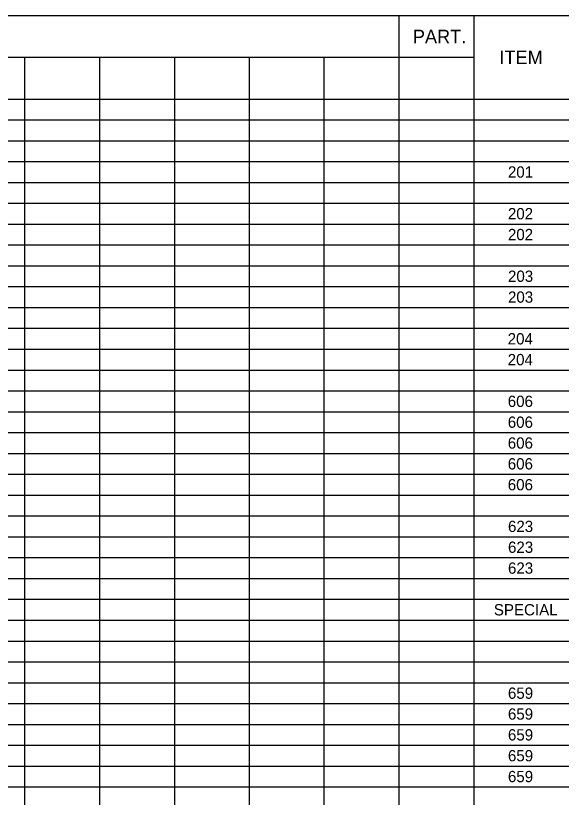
# Model space of a CAD drawing. Extents: x -31.7 to 37.3, y 0 to 22.
# Drawn here: x -23.79 to -16.46, y 10.82 to 21.32 of the extents above; entities that cross this region are included whole.
import ezdxf

# ---------------------------------------------------------------- set-up
doc = ezdxf.new("R2010")
doc.units = 0
doc.layers.add('Default', color=7, linetype='Continuous')

msp = doc.modelspace()

# ---------------------------------------------------------------- linework, layer by layer
at = {"layer": 'Default'}
for p, q in [((-31.705, 21.321), (-1.202, 21.321)), ((-18.644, 21.321), (-18.644, 0.321)), ((-17.639, 21.321), (-17.639, 0.321)), ((-31.705, 20.761), (-17.639, 20.761)), ((-23.668, 20.761), (-23.668, 0.321)), ((-22.663, 20.761), (-22.663, 0.321)), ((-21.658, 20.761), (-21.658, 0.321)), ((-20.653, 20.761), (-20.653, 0.321)), ((-19.649, 20.761), (-19.649, 0.321)), ((-31.705, 20.201), (-1.202, 20.201)), ((-31.705, 19.921), (-1.202, 19.921)), ((-31.705, 19.641), (-1.202, 19.641)), ((-31.705, 19.361), (-1.202, 19.361)), ((-31.705, 19.081), (-1.202, 19.081)), ((-31.705, 18.801), (-1.202, 18.801)), ((-31.705, 18.521), (-1.202, 18.521)), ((-31.705, 18.241), (-1.202, 18.241)), ((-31.705, 17.961), (-1.202, 17.961)), ((-31.705, 17.681), (-1.202, 17.681)), ((-31.705, 17.401), (-1.202, 17.401)), ((-31.705, 17.121), (-1.202, 17.121)), ((-31.705, 16.841), (-1.202, 16.841)), ((-31.705, 16.561), (-1.202, 16.561)), ((-31.705, 16.281), (-1.202, 16.281)), ((-31.705, 16.001), (-1.202, 16.001)), ((-31.705, 15.721), (-1.202, 15.721)), ((-31.705, 15.441), (-1.202, 15.441)), ((-31.705, 15.161), (-1.202, 15.161)), ((-31.705, 14.881), (-1.202, 14.881)), ((-31.705, 14.601), (-1.202, 14.601)), ((-31.705, 14.321), (-1.202, 14.321)), ((-31.705, 14.041), (-1.202, 14.041)), ((-31.705, 13.761), (-1.202, 13.761)), ((-31.705, 13.481), (-1.202, 13.481)), ((-31.705, 13.201), (-1.202, 13.201)), ((-31.705, 12.921), (-1.202, 12.921)), ((-31.705, 12.641), (-1.202, 12.641)), ((-31.705, 12.361), (-1.202, 12.361)), ((-31.705, 12.081), (-1.202, 12.081)), ((-31.705, 11.801), (-1.202, 11.801)), ((-31.705, 11.521), (-1.202, 11.521)), ((-31.705, 11.241), (-1.202, 11.241)), ((-31.705, 10.961), (-1.202, 10.961))]:
    msp.add_line(p, q, dxfattribs=at)

# ---------------------------------------------------------------- texts
for s, height, p in [('PART.', 0.1818, (-18.455, 20.95)), ('ITEM', 0.1818, (-17.293, 20.67)), ('201', 0.1515, (-17.179, 19.145)), ('202', 0.1515, (-17.179, 18.585)), ('202', 0.1515, (-17.179, 18.305)), ('203', 0.1515, (-17.178, 17.745)), ('203', 0.1515, (-17.178, 17.465)), ('204', 0.1515, (-17.182, 16.905)), ('204', 0.1515, (-17.182, 16.625)), ('606', 0.1515, (-17.181, 16.065)), ('606', 0.1515, (-17.181, 15.785)), ('606', 0.1515, (-17.181, 15.505)), ('606', 0.1515, (-17.181, 15.225)), ('606', 0.1515, (-17.181, 14.945)), ('623', 0.1515, (-17.178, 14.385)), ('623', 0.1515, (-17.178, 14.105)), ('623', 0.1515, (-17.178, 13.825)), ('SPECIAL', 0.1515, (-17.368, 13.265)), ('659', 0.1515, (-17.179, 12.145)), ('659', 0.1515, (-17.179, 11.865)), ('659', 0.1515, (-17.179, 11.585)), ('659', 0.1515, (-17.179, 11.305)), ('659', 0.1515, (-17.179, 11.025))]:
    msp.add_text(s, height=height, dxfattribs=at).set_placement(p)

doc.saveas('drawing.dxf')
